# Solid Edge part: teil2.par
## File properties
Author: Susi
Template: Normal.par
Last saved by: Susi
Revision: 1
Application: Solid Edge
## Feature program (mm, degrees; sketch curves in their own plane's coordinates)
sketch for "unnamed Protrusion 1" plane through (0, 0, 0) normal (0, 0, 1) x-axis (1, 0, 0)
extrude "unnamed Protrusion 1" add finite 10 along +normal
sketch for "unnamed Cutout 1" #1 plane through (0, 0, 0) normal (0, 0, 1) x-axis (1, 0, 0)
  circle centre (20, 45) radius 10
sketch for "unnamed Cutout 1" #2 plane through (0, 0, 0) normal (0, 0, 1) x-axis (1, 0, 0)
  circle centre (20, 70) radius 10
sketch for "unnamed Cutout 1" #3 plane through (0, 0, 0) normal (0, 0, 1) x-axis (1, 0, 0)
  circle centre (20, 20) radius 10
extrude "unnamed Cutout 1" cut finite 88.9 symmetric
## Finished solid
Body 1: solid body, 9 faces, 18 edges, 8 vertices.
  Faces by surface: plane 6, cylinder 3
  Edges by curve: line 12, circle 6
Bounding box of the edges (mm): 40.000 x 90.000 x 10.000, from (0, 0, 0) to (40, 90, 10).
Cylindrical faces by radius (mm): R10 x3
Planar faces by outward normal: +x 1, +y 1, +z 1, -x 1, -y 1, -z 1
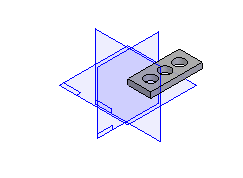
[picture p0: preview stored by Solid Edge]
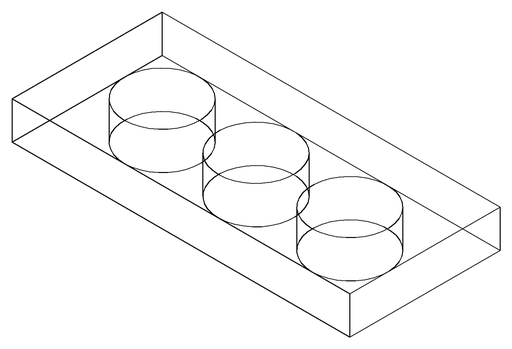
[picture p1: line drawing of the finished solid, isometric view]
